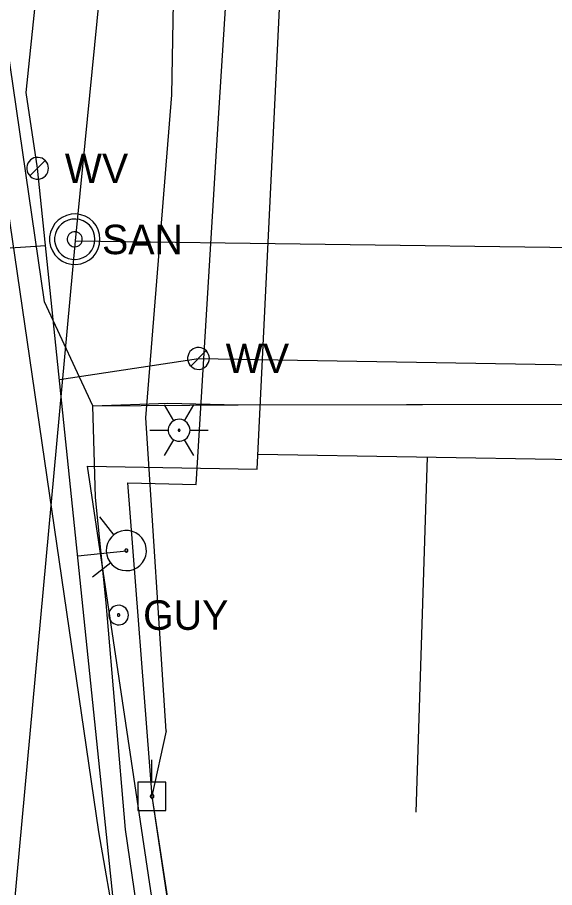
# Model space of a CAD drawing. Extents: x 600849 to 606371, y 330010 to 403088.
# Drawn here: x 604924.2 to 604994.4, y 335762 to 335875.8 of the extents above; entities that cross this region are included whole.
import ezdxf

# ---------------------------------------------------------------- set-up
doc = ezdxf.new("R2010")
doc.units = 0
for name, color, linetype in [('E_LTG', 7, 'Continuous'), ('E_UTL_E_UG', 7, 'Continuous'), ('E_UTL_EGuyWire', 7, 'Continuous'), ('E_UTL_EPowerPole', 7, 'Continuous'), ('E_UTL_G_UG', 7, 'Continuous'), ('E_UTL_Overhead', 7, 'Continuous'), ('E_UTL_SAN', 7, 'Continuous'), ('E_UTL_SAN_UG', 7, 'Continuous'), ('E_UTL_TV_UG', 7, 'Continuous'), ('E_UTL_W', 7, 'Continuous'), ('E_UTL_W_UG', 7, 'Continuous'), ('E_UTL_WHydrant', 7, 'Continuous')]:
    doc.layers.add(name, color=color, linetype=linetype)

msp = doc.modelspace()

# ---------------------------------------------------------------- linework, layer by layer
at = {"layer": 'E_LTG'}
for points in [[(604944.59, 335823.04), (604943.39, 335825.1)], [(604946.01, 335823.04), (604947.21, 335825.1)], [(604946.73, 335821.8), (604946.7, 335822.07), (604946.63, 335822.33), (604946.5, 335822.57), (604946.33, 335822.78), (604946.13, 335822.96), (604945.89, 335823.1), (604945.64, 335823.19), (604945.37, 335823.23), (604945.1, 335823.21), (604944.83, 335823.15), (604944.59, 335823.04), (604944.36, 335822.88), (604944.18, 335822.68), (604944.03, 335822.45), (604943.93, 335822.2), (604943.88, 335821.93), (604943.88, 335821.66), (604943.93, 335821.4), (604944.03, 335821.14), (604944.18, 335820.92), (604944.36, 335820.72), (604944.59, 335820.56), (604944.83, 335820.45), (604945.1, 335820.38), (604945.37, 335820.37), (604945.64, 335820.41), (604945.89, 335820.5), (604946.13, 335820.63), (604946.33, 335820.81), (604946.5, 335821.03), (604946.63, 335821.27), (604946.7, 335821.53), (604946.73, 335821.8)], [(604946.73, 335821.8), (604946.7, 335822.07), (604946.63, 335822.33), (604946.5, 335822.57), (604946.33, 335822.78), (604946.13, 335822.96), (604945.89, 335823.1), (604945.64, 335823.19), (604945.37, 335823.23), (604945.1, 335823.21), (604944.83, 335823.15), (604944.59, 335823.04), (604944.36, 335822.88), (604944.18, 335822.68), (604944.03, 335822.45), (604943.93, 335822.2), (604943.88, 335821.93), (604943.88, 335821.66), (604943.93, 335821.4), (604944.03, 335821.14), (604944.18, 335820.92), (604944.36, 335820.72), (604944.59, 335820.56), (604944.83, 335820.45), (604945.1, 335820.38), (604945.37, 335820.37), (604945.64, 335820.41), (604945.89, 335820.5), (604946.13, 335820.63), (604946.33, 335820.81), (604946.5, 335821.03), (604946.63, 335821.27), (604946.7, 335821.53), (604946.73, 335821.8)], [(604946.73, 335821.8), (604946.7, 335822.07), (604946.63, 335822.33), (604946.5, 335822.57), (604946.33, 335822.78), (604946.13, 335822.96), (604945.89, 335823.1), (604945.64, 335823.19), (604945.37, 335823.23), (604945.1, 335823.21), (604944.83, 335823.15), (604944.59, 335823.04), (604944.36, 335822.88), (604944.18, 335822.68), (604944.03, 335822.45), (604943.93, 335822.2), (604943.88, 335821.93), (604943.88, 335821.66), (604943.93, 335821.4), (604944.03, 335821.14), (604944.18, 335820.92), (604944.36, 335820.72), (604944.59, 335820.56), (604944.83, 335820.45), (604945.1, 335820.38), (604945.37, 335820.37), (604945.64, 335820.41), (604945.89, 335820.5), (604946.13, 335820.63), (604946.33, 335820.81), (604946.5, 335821.03), (604946.63, 335821.27), (604946.7, 335821.53), (604946.73, 335821.8)], [(604941.49, 335821.8), (604943.87, 335821.8)], [(604945.42, 335821.8), (604945.42, 335821.82), (604945.41, 335821.84), (604945.4, 335821.86), (604945.39, 335821.88), (604945.37, 335821.9), (604945.35, 335821.91), (604945.33, 335821.91), (604945.31, 335821.92), (604945.28, 335821.92), (604945.26, 335821.91), (604945.24, 335821.9), (604945.22, 335821.89), (604945.21, 335821.87), (604945.19, 335821.85), (604945.19, 335821.83), (604945.18, 335821.81), (604945.18, 335821.79), (604945.19, 335821.76), (604945.19, 335821.74), (604945.21, 335821.72), (604945.22, 335821.71), (604945.24, 335821.7), (604945.26, 335821.69), (604945.28, 335821.68), (604945.31, 335821.68), (604945.33, 335821.68), (604945.35, 335821.69), (604945.37, 335821.7), (604945.39, 335821.72), (604945.4, 335821.73), (604945.41, 335821.75), (604945.42, 335821.78), (604945.42, 335821.8)], [(604946.73, 335821.8), (604949.11, 335821.8)], [(604943.39, 335818.5), (604944.59, 335820.56)], [(604947.21, 335818.5), (604946.01, 335820.56)]]:
    msp.add_lwpolyline(points, dxfattribs=at)
at = {"layer": 'E_UTL_E_UG'}
for points in [[(604950.37, 335861.21), (604952.66, 335897.52), (604957.54, 335971.28), (604966.18, 336031.51), (604975.9, 336071.51), (604986.04, 336114.11), (605001.87, 336168.57), (605008.63, 336196.68)], [(604941.77, 335773.97), (604938.58, 335814.91), (604947.51, 335814.7), (604950.37, 335861.21)]]:
    msp.add_lwpolyline(points, dxfattribs=at)
at = {"layer": 'E_UTL_EGuyWire'}
for points in [[(604938.66, 335797.65), (604938.64, 335797.89), (604938.57, 335798.13), (604938.46, 335798.34), (604938.31, 335798.53), (604938.12, 335798.69), (604937.91, 335798.82), (604937.68, 335798.9), (604937.44, 335798.93), (604937.2, 335798.92), (604936.96, 335798.86), (604936.74, 335798.76), (604936.54, 335798.62), (604936.37, 335798.44), (604936.24, 335798.24), (604936.15, 335798.01), (604936.1, 335797.77), (604936.1, 335797.53), (604936.15, 335797.29), (604936.24, 335797.06), (604936.37, 335796.86), (604936.54, 335796.68), (604936.74, 335796.54), (604936.96, 335796.44), (604937.2, 335796.38), (604937.44, 335796.37), (604937.68, 335796.4), (604937.91, 335796.48), (604938.12, 335796.6), (604938.31, 335796.76), (604938.46, 335796.95), (604938.57, 335797.17), (604938.64, 335797.41), (604938.66, 335797.65)], [(604937.54, 335797.65), (604937.54, 335797.68), (604937.53, 335797.71), (604937.52, 335797.74), (604937.5, 335797.76), (604937.47, 335797.78), (604937.45, 335797.79), (604937.42, 335797.8), (604937.39, 335797.81), (604937.36, 335797.81), (604937.33, 335797.8), (604937.3, 335797.79), (604937.28, 335797.77), (604937.25, 335797.75), (604937.24, 335797.72), (604937.23, 335797.69), (604937.22, 335797.66), (604937.22, 335797.63), (604937.23, 335797.6), (604937.24, 335797.57), (604937.25, 335797.55), (604937.28, 335797.53), (604937.3, 335797.51), (604937.33, 335797.5), (604937.36, 335797.49), (604937.39, 335797.49), (604937.42, 335797.49), (604937.45, 335797.5), (604937.47, 335797.52), (604937.5, 335797.54), (604937.52, 335797.56), (604937.53, 335797.59), (604937.54, 335797.62), (604937.54, 335797.65)]]:
    msp.add_lwpolyline(points, dxfattribs=at)
at = {"layer": 'E_UTL_EPowerPole'}
for points in [[(604941.74, 335775.81), (604941.74, 335778.72)], [(604943.58, 335775.81), (604939.89, 335775.81)], [(604939.89, 335775.81), (604939.89, 335772.12)], [(604943.58, 335772.12), (604943.58, 335775.81)], [(604942.01, 335773.97), (604942, 335774.01), (604941.99, 335774.06), (604941.97, 335774.1), (604941.94, 335774.13), (604941.91, 335774.16), (604941.87, 335774.19), (604941.83, 335774.2), (604941.78, 335774.21), (604941.74, 335774.2), (604941.69, 335774.19), (604941.65, 335774.17), (604941.61, 335774.15), (604941.58, 335774.12), (604941.56, 335774.08), (604941.54, 335774.04), (604941.53, 335773.99), (604941.53, 335773.95), (604941.54, 335773.9), (604941.56, 335773.86), (604941.58, 335773.82), (604941.61, 335773.79), (604941.65, 335773.76), (604941.69, 335773.74), (604941.74, 335773.73), (604941.78, 335773.73), (604941.83, 335773.74), (604941.87, 335773.75), (604941.91, 335773.77), (604941.94, 335773.8), (604941.97, 335773.84), (604941.99, 335773.88), (604942, 335773.92), (604942.01, 335773.97)], [(604939.89, 335772.12), (604943.58, 335772.12)]]:
    msp.add_lwpolyline(points, dxfattribs=at)
at = {"layer": 'E_UTL_G_UG'}
for p, q in [((604934.01, 335824.97), (604953.01, 335825.14)), ((604953.01, 335825.14), (605121.78, 335825.42)), ((604955.62, 335818.69), (605142.02, 335815.42)), ((604976.3, 335771.9), (604977.79, 335818.3))]:
    msp.add_line(p, q, dxfattribs=at)
for points in [[(604933.3, 335817.09), (604955.52, 335816.7), (604962, 335950.57), (604915.78, 335952.81)], [(604992.54, 335374.29), (604982.41, 335439.85), (604977.55, 335472.28), (604967.89, 335533.23), (604963.9, 335558.28), (604960.62, 335582.14), (604958.16, 335603.66), (604954.67, 335636.73), (604949.76, 335671.68), (604943.72, 335708.39), (604939.44, 335742.84), (604934.8, 335769.3), (604917.37, 335888.66), (604913.54, 335917.13), (604913.36, 335918.56), (604912.73, 335934.03), (604913.24, 335947.88)], [(604934.01, 335824.97), (604927.71, 335838.6), (604920.34, 335889.07), (604916.51, 335917.52), (604916.35, 335918.82), (604915.73, 335934.04), (604915.75, 335942.13)], [(604934.01, 335824.97), (604927.71, 335838.6), (604920.34, 335889.07), (604916.51, 335917.52), (604916.35, 335918.82), (604915.73, 335934.04), (604915.75, 335942.13)], [(604990.22, 335373.94), (604984.89, 335440.46), (604980.73, 335472.71), (604971.32, 335533.67), (604967.23, 335558.65), (604963.42, 335582.81), (604960.7, 335604.2), (604956.77, 335636.76), (604952.03, 335671.62), (604946.45, 335709.05), (604942.07, 335743.65), (604938.29, 335769.61), (604935.75, 335799.26), (604934.37, 335813.01), (604934.01, 335824.97), (604943.83, 335825.34), (604953.01, 335825.14)], [(604990.22, 335373.94), (604984.89, 335440.46), (604980.73, 335472.71), (604971.32, 335533.67), (604967.23, 335558.65), (604963.42, 335582.81), (604960.7, 335604.2), (604956.77, 335636.76), (604952.03, 335671.62), (604946.45, 335709.05), (604942.07, 335743.65), (604938.29, 335769.61), (604935.75, 335799.26), (604934.37, 335813.01), (604934.01, 335824.97), (604943.83, 335825.34), (604953.01, 335825.14)], [(604953.01, 335825.14), (605121.78, 335825.42)], [(604969.99, 335561.13), (604966.54, 335588.97), (604950.9, 335699.39), (604933.3, 335817.09)]]:
    msp.add_lwpolyline(points, dxfattribs=at)
at = {"layer": 'E_UTL_Overhead'}
msp.add_lwpolyline([(605062.13, 334030.34), (605053.67, 334169.81), (605046.99, 334304.15), (605041.52, 334434.58), (605034.02, 334560.2), (605027.64, 334680.76), (605025.35, 334737.63), (605023.22, 334807.38), (605018.57, 334937.28), (605013.93, 335101.09), (605004.43, 335294.31), (604985.51, 335452.18), (604968.52, 335589.23), (604952.88, 335699.68), (604941.77, 335773.97)], dxfattribs=at)
at = {"layer": 'E_UTL_SAN'}
for points in [[(604934.95, 335846.76), (604934.89, 335847.38), (604934.72, 335847.99), (604934.43, 335848.54), (604934.04, 335849.04), (604933.57, 335849.45), (604933.02, 335849.76), (604932.43, 335849.97), (604931.81, 335850.06), (604931.18, 335850.03), (604930.57, 335849.88), (604930, 335849.62), (604929.49, 335849.25), (604929.06, 335848.8), (604928.72, 335848.27), (604928.49, 335847.69), (604928.37, 335847.07), (604928.37, 335846.45), (604928.49, 335845.83), (604928.72, 335845.25), (604929.06, 335844.72), (604929.49, 335844.27), (604930, 335843.9), (604930.57, 335843.64), (604931.18, 335843.49), (604931.81, 335843.46), (604932.43, 335843.55), (604933.02, 335843.76), (604933.57, 335844.07), (604934.04, 335844.48), (604934.43, 335844.98), (604934.72, 335845.53), (604934.89, 335846.13), (604934.95, 335846.76)], [(604934.29, 335846.76), (604934.24, 335847.26), (604934.1, 335847.74), (604933.87, 335848.19), (604933.56, 335848.58), (604933.18, 335848.91), (604932.75, 335849.16), (604932.27, 335849.33), (604931.78, 335849.4), (604931.28, 335849.37), (604930.79, 335849.25), (604930.33, 335849.05), (604929.92, 335848.75), (604929.58, 335848.39), (604929.31, 335847.97), (604929.12, 335847.5), (604929.02, 335847.01), (604929.02, 335846.51), (604929.12, 335846.02), (604929.31, 335845.55), (604929.58, 335845.13), (604929.92, 335844.76), (604930.33, 335844.47), (604930.79, 335844.26), (604931.28, 335844.15), (604931.78, 335844.12), (604932.27, 335844.19), (604932.75, 335844.36), (604933.18, 335844.61), (604933.56, 335844.94), (604933.87, 335845.33), (604934.1, 335845.78), (604934.24, 335846.26), (604934.29, 335846.76)], [(604932.64, 335846.76), (604932.62, 335846.95), (604932.57, 335847.13), (604932.48, 335847.29), (604932.37, 335847.44), (604932.23, 335847.57), (604932.06, 335847.66), (604931.89, 335847.72), (604931.7, 335847.75), (604931.51, 335847.74), (604931.33, 335847.7), (604931.16, 335847.62), (604931, 335847.51), (604930.87, 335847.37), (604930.77, 335847.21), (604930.7, 335847.04), (604930.67, 335846.85), (604930.67, 335846.67), (604930.7, 335846.48), (604930.77, 335846.31), (604930.87, 335846.15), (604931, 335846.01), (604931.16, 335845.9), (604931.33, 335845.82), (604931.51, 335845.78), (604931.7, 335845.77), (604931.89, 335845.8), (604932.06, 335845.86), (604932.23, 335845.95), (604932.37, 335846.08), (604932.48, 335846.22), (604932.57, 335846.39), (604932.62, 335846.57), (604932.64, 335846.76)]]:
    msp.add_lwpolyline(points, dxfattribs=at)
at = {"layer": 'E_UTL_SAN_UG'}
for p, q in [((604931.74, 335846.56), (604948.46, 336015.86)), ((604909.37, 335602.98), (604931.74, 335846.56)), ((604931.74, 335846.56), (605113.4, 335844.14))]:
    msp.add_line(p, q, dxfattribs=at)
at = {"layer": 'E_UTL_TV_UG'}
msp.add_lwpolyline([(604952.88, 335699.68), (604947.56, 335736.19), (604941.77, 335773.97), (604943.64, 335782.51), (604943.62, 335782.47), (604940.93, 335823.43), (604944.35, 335865.62), (604944.84, 335892.26), (604946.69, 335923.37), (604951.72, 335970.22), (604956.7, 336009.43), (604966.16, 336057), (604981.4, 336117.37), (604995.05, 336168.57), (604995.08, 336168.59), (605002.88, 336192.51), (605017.85, 336240.31), (605030.14, 336283.75), (605041.76, 336326.86), (605047.54, 336347.25), (605060.52, 336404.97)], dxfattribs=at)
at = {"layer": 'E_UTL_W'}
for points in [[(604928.22, 335856.04), (604928.19, 335856.31), (604928.11, 335856.57), (604927.99, 335856.81), (604927.82, 335857.02), (604927.62, 335857.2), (604927.38, 335857.34), (604927.13, 335857.42), (604926.86, 335857.46), (604926.59, 335857.45), (604926.32, 335857.39), (604926.08, 335857.27), (604925.86, 335857.12), (604925.67, 335856.92), (604925.52, 335856.69), (604925.42, 335856.44), (604925.37, 335856.17), (604925.37, 335855.9), (604925.42, 335855.64), (604925.52, 335855.39), (604925.67, 335855.16), (604925.86, 335854.96), (604926.08, 335854.8), (604926.32, 335854.69), (604926.59, 335854.63), (604926.86, 335854.61), (604927.13, 335854.65), (604927.38, 335854.74), (604927.62, 335854.88), (604927.82, 335855.05), (604927.99, 335855.27), (604928.11, 335855.51), (604928.19, 335855.77), (604928.22, 335856.04)], [(604925.78, 335855.03), (604927.8, 335857.05)], [(604949.26, 335831.19), (604949.23, 335831.46), (604949.15, 335831.72), (604949.03, 335831.96), (604948.86, 335832.17), (604948.66, 335832.35), (604948.42, 335832.49), (604948.17, 335832.57), (604947.9, 335832.61), (604947.63, 335832.6), (604947.36, 335832.54), (604947.12, 335832.42), (604946.9, 335832.27), (604946.71, 335832.07), (604946.56, 335831.84), (604946.46, 335831.59), (604946.41, 335831.32), (604946.41, 335831.05), (604946.46, 335830.79), (604946.56, 335830.54), (604946.71, 335830.31), (604946.9, 335830.11), (604947.12, 335829.95), (604947.36, 335829.84), (604947.63, 335829.78), (604947.9, 335829.76), (604948.17, 335829.8), (604948.42, 335829.89), (604948.66, 335830.03), (604948.86, 335830.2), (604949.03, 335830.42), (604949.15, 335830.66), (604949.23, 335830.92), (604949.26, 335831.19)], [(604946.82, 335830.18), (604948.84, 335832.2)]]:
    msp.add_lwpolyline(points, dxfattribs=at)
at = {"layer": 'E_UTL_W_UG'}
for p, q in [((604929.65, 335828.45), (604947.83, 335831.19)), ((604947.83, 335831.19), (605080.34, 335828.87)), ((604932.04, 335805.39), (604938.4, 335806.05))]:
    msp.add_line(p, q, dxfattribs=at)
for points in [[(604926.79, 335856.04), (604925.3, 335865.93), (604950.66, 336110.15)], [(604940.12, 335727.35), (604926.79, 335856.04)], [(604889.64, 335843.41), (604927.84, 335845.94)]]:
    msp.add_lwpolyline(points, dxfattribs=at)
at = {"layer": 'E_UTL_WHydrant'}
for points in [[(604936.79, 335808.11), (604934.91, 335810.49)], [(604938.7, 335808.68), (604938.2, 335808.69), (604937.71, 335808.61), (604937.25, 335808.43), (604936.82, 335808.17), (604936.45, 335807.84), (604936.16, 335807.44), (604935.94, 335806.99), (604935.81, 335806.51), (604935.78, 335806.01), (604935.84, 335805.51), (604935.99, 335805.04), (604936.23, 335804.6), (604936.55, 335804.22), (604936.94, 335803.9), (604937.37, 335803.66), (604937.85, 335803.51), (604938.35, 335803.46), (604938.84, 335803.49), (604939.32, 335803.62), (604939.77, 335803.84), (604940.17, 335804.14), (604940.5, 335804.51), (604940.76, 335804.94), (604940.94, 335805.41), (604941.02, 335805.9), (604941, 335806.4), (604940.9, 335806.88), (604940.7, 335807.34), (604940.42, 335807.75), (604940.06, 335808.11), (604939.65, 335808.38), (604939.19, 335808.58), (604938.7, 335808.68)], [(604938.42, 335806.28), (604938.38, 335806.28), (604938.35, 335806.27), (604938.31, 335806.26), (604938.28, 335806.24), (604938.25, 335806.21), (604938.23, 335806.18), (604938.21, 335806.15), (604938.2, 335806.11), (604938.2, 335806.07), (604938.2, 335806.03), (604938.22, 335806), (604938.23, 335805.97), (604938.26, 335805.94), (604938.29, 335805.91), (604938.32, 335805.89), (604938.36, 335805.88), (604938.4, 335805.88), (604938.43, 335805.88), (604938.47, 335805.89), (604938.5, 335805.91), (604938.54, 335805.93), (604938.56, 335805.96), (604938.58, 335805.99), (604938.59, 335806.03), (604938.6, 335806.06), (604938.6, 335806.1), (604938.59, 335806.14), (604938.58, 335806.17), (604938.55, 335806.21), (604938.53, 335806.23), (604938.5, 335806.25), (604938.46, 335806.27), (604938.42, 335806.28)], [(604936.36, 335804.47), (604933.99, 335802.59)]]:
    msp.add_lwpolyline(points, dxfattribs=at)

# ---------------------------------------------------------------- texts
at = {"layer": 'E_UTL_EGuyWire'}
msp.add_text('GUY', height=3.85, dxfattribs=at).set_placement((604940.59, 335795.72))
at = {"layer": 'E_UTL_SAN'}
msp.add_text('SAN', height=3.849, dxfattribs=at).set_placement((604935.22, 335844.81))
at = {"layer": 'E_UTL_W'}
for p in [(604930.35, 335854.11), (604951.39, 335829.26)]:
    msp.add_text('WV', height=3.85, dxfattribs=at).set_placement(p)

doc.saveas('drawing.dxf')
